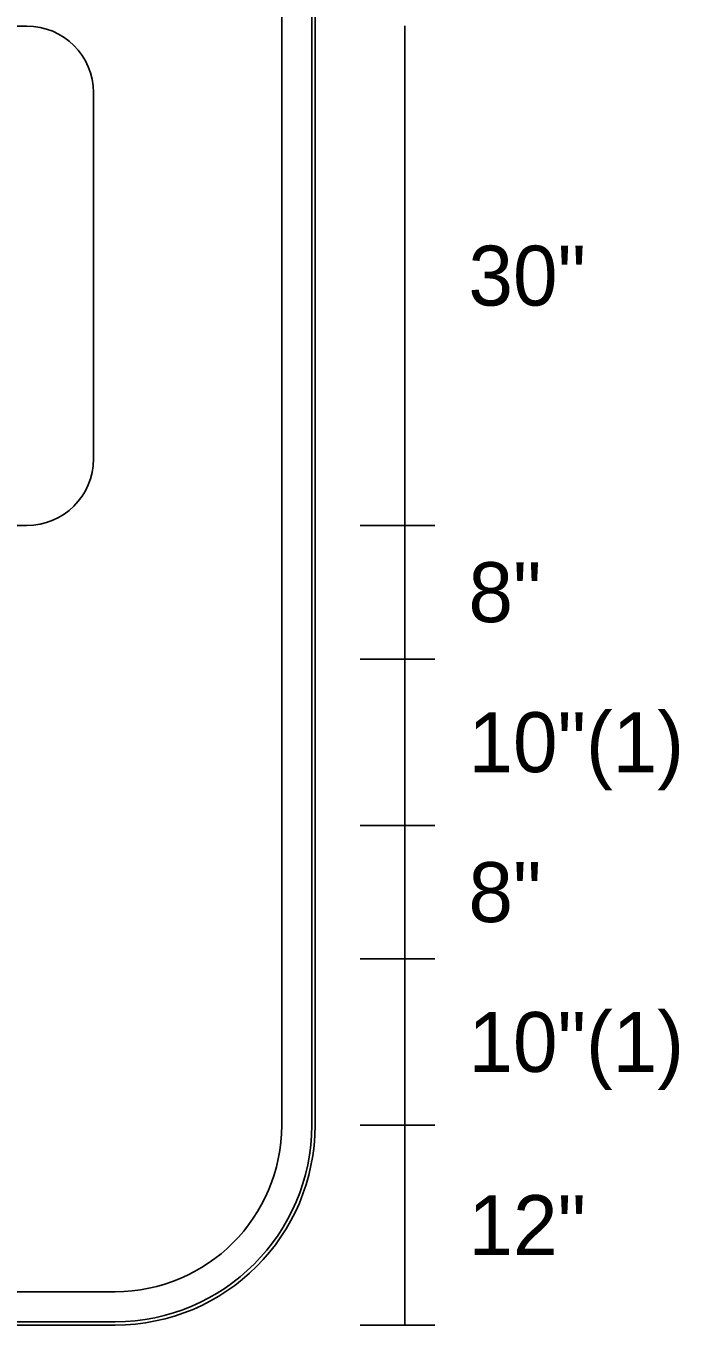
# Model space of a CAD drawing. Extents: x 10268312 to 10268471, y 2141099 to 2141204.
# Drawn here: x 10268418.36 to 10268426.53, y 2141131.78 to 2141148.03 of the extents above; entities that cross this region are included whole.
import ezdxf

# ---------------------------------------------------------------- set-up
doc = ezdxf.new("R2010")
doc.units = 0
for name, color, linetype in [('GSBWFill', 7, 'Continuous'), ('GSColorFill', 7, 'Continuous'), ('GSDims', 7, 'Continuous'), ('GSOutline', 7, 'Continuous')]:
    doc.layers.add(name, color=color, linetype=linetype)

msp = doc.modelspace()

# ---------------------------------------------------------------- linework, layer by layer
at = {"layer": 'GSBWFill'}
for p, q in [((10268421.564, 2141155.528), (10268421.564, 2141134.278)), ((10268421.98, 2141134.278), (10268421.98, 2141155.528)), ((10268402.54, 2141148.032), (10268418.374, 2141148.032)), ((10268419.207, 2141147.199), (10268419.207, 2141142.615)), ((10268418.374, 2141141.782), (10268402.54, 2141141.782)), ((10268419.48, 2141132.195), (10268393.234, 2141132.195)), ((10268393.234, 2141131.778), (10268419.48, 2141131.778))]:
    msp.add_line(p, q, dxfattribs=at)
for centre, radius, start, end in [((10268418.374, 2141147.199), 0.833, 0, 90), ((10268418.374, 2141142.615), 0.833, 270, 0), ((10268419.48, 2141134.278), 2.5, 270, 0), ((10268419.48, 2141134.278), 2.083, 270, 0)]:
    msp.add_arc(centre, radius, start, end, dxfattribs=at)
at = {"layer": 'GSColorFill'}
for p, q in [((10268421.564, 2141155.528), (10268421.564, 2141134.278)), ((10268421.939, 2141155.528), (10268421.939, 2141134.278)), ((10268421.98, 2141134.278), (10268421.98, 2141155.528)), ((10268421.98, 2141134.278), (10268421.98, 2141155.528)), ((10268421.98, 2141134.278), (10268421.98, 2141155.528)), ((10268419.48, 2141132.195), (10268393.234, 2141132.195)), ((10268393.23, 2141131.778), (10268419.48, 2141131.778)), ((10268419.48, 2141131.82), (10268393.231, 2141131.82)), ((10268393.231, 2141131.778), (10268419.48, 2141131.778)), ((10268393.234, 2141131.778), (10268419.48, 2141131.778))]:
    msp.add_line(p, q, dxfattribs=at)
for radius in [2.5, 2.5, 2.083, 2.5, 2.458]:
    msp.add_arc((10268419.48, 2141134.278), radius, 270, 0, dxfattribs=at)
at = {"layer": 'GSDims'}
for p, q in [((10268423.105, 2141148.034), (10268423.105, 2141141.784)), ((10268422.543, 2141141.784), (10268423.48, 2141141.784)), ((10268422.543, 2141141.784), (10268423.48, 2141141.784)), ((10268423.105, 2141140.112), (10268423.105, 2141141.784)), ((10268422.543, 2141140.112), (10268423.48, 2141140.112)), ((10268422.543, 2141140.112), (10268423.48, 2141140.112)), ((10268423.105, 2141140.112), (10268423.105, 2141138.029)), ((10268422.543, 2141138.029), (10268423.48, 2141138.029)), ((10268422.543, 2141138.029), (10268423.48, 2141138.029)), ((10268423.105, 2141136.362), (10268423.105, 2141138.029)), ((10268422.543, 2141136.362), (10268423.48, 2141136.362)), ((10268423.105, 2141136.362), (10268423.105, 2141134.278)), ((10268422.543, 2141134.278), (10268423.48, 2141134.278)), ((10268423.105, 2141134.278), (10268423.105, 2141131.778)), ((10268422.543, 2141131.778), (10268423.48, 2141131.778))]:
    msp.add_line(p, q, dxfattribs=at)
at = {"layer": 'GSOutline'}
for p, q in [((10268421.564, 2141134.278), (10268421.564, 2141155.528)), ((10268421.98, 2141134.278), (10268421.98, 2141155.528)), ((10268393.23, 2141132.195), (10268419.48, 2141132.195)), ((10268393.23, 2141131.778), (10268419.48, 2141131.778))]:
    msp.add_line(p, q, dxfattribs=at)
for radius in [2.5, 2.083]:
    msp.add_arc((10268419.48, 2141134.278), radius, 270, 0, dxfattribs=at)

# ---------------------------------------------------------------- texts
at = {"layer": 'GSDims'}
for s, p in [('30"', (10268423.899, 2141144.534)), ('8"', (10268423.899, 2141140.573)), ('10"(1)', (10268423.899, 2141138.696)), ('8"', (10268423.899, 2141136.82)), ('10"(1)', (10268423.899, 2141134.945)), ('12"', (10268423.899, 2141132.653))]:
    msp.add_text(s, height=0.75, dxfattribs=at).set_placement(p)

doc.saveas('drawing.dxf')
